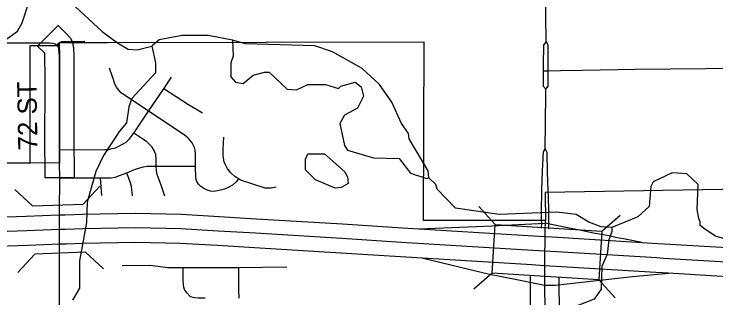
# Model space of a CAD drawing. Extents: x -1403959 to 81668, y -1400582 to 11018.
# Drawn here: x 6695.1 to 6835.6, y 8666.3 to 8723.2 of the extents above; entities that cross this region are included whole.
import ezdxf

# ---------------------------------------------------------------- set-up
doc = ezdxf.new("R2010")
doc.units = 0
for name, color, linetype in [('tdCiAirportTxt', 7, 'Continuous'), ('tdCiCityCartoShort', 7, 'Continuous'), ('tdCiCityDivCarto', 7, 'Continuous'), ('tdCiCityStreetTxt', 7, 'Continuous'), ('tdCiCoBndryTxt', 7, 'Continuous'), ('tdCiRRCL', 7, 'Continuous'), ('tdCiSectLine', 7, 'Continuous'), ('tdCiSectNmbr', 7, 'Continuous'), ('tdCiSectTwpRng', 7, 'Continuous'), ('tdCoCityStreetMajor', 7, 'Continuous'), ('tdCoDivCarto', 7, 'Continuous'), ('tdCoPriCL', 7, 'Continuous'), ('tdCoSectNmbr', 7, 'Continuous'), ('tdCoSurfBitum', 7, 'Continuous'), ('tdCoSurfEarth', 7, 'Continuous')]:
    doc.layers.add(name, color=color, linetype=linetype)

msp = doc.modelspace()

# ---------------------------------------------------------------- linework, layer by layer
at = {"layer": 'tdCiAirportTxt'}
for points in [[(6656.54, 8681.26), (6697.52, 8682.67), (6704.05, 8682.91), (6705.25, 8682.95), (6705.29, 8682.95), (6708.75, 8683.09), (6719.41, 8683.29), (6728.58, 8683.07), (6736.15, 8682.63), (6743.59, 8682.17), (6760.88, 8681.11), (6772.85, 8680.35), (6799.13, 8678.75), (6801.54, 8678.6), (6803.99, 8678.45), (6823.98, 8677.22), (6825.34, 8677.14), (6845.86, 8675.9)], [(6656.78, 8675.47), (6697.73, 8676.87), (6704.27, 8677.11), (6705.47, 8677.15), (6705.51, 8677.15), (6708.92, 8677.28), (6719.4, 8677.49), (6728.34, 8677.27), (6735.8, 8676.83), (6743.24, 8676.38), (6760.52, 8675.32), (6772.49, 8674.56), (6798.77, 8672.96), (6801.19, 8672.81), (6803.64, 8672.66), (6823.61, 8671.43), (6824.98, 8671.35), (6845.51, 8670.11)]]:
    msp.add_lwpolyline(points, dxfattribs=at)
at = {"layer": 'tdCiCityCartoShort'}
msp.add_lwpolyline([(6845.68, 8672.98), (6825.15, 8674.21), (6823.79, 8674.3), (6803.81, 8675.53), (6801.36, 8675.68), (6798.94, 8675.82), (6772.66, 8677.42), (6760.69, 8678.18), (6743.41, 8679.25), (6735.97, 8679.7), (6728.46, 8680.14), (6719.4, 8680.36), (6708.83, 8680.16), (6705.39, 8680.03), (6705.35, 8680.02), (6704.15, 8679.98), (6697.62, 8679.74), (6656.66, 8678.34)], dxfattribs=at)
at = {"layer": 'tdCiCityDivCarto'}
for points in [[(6802.08, 8686.96), (6802.07, 8687.43)], [(6802.09, 8686.82), (6802.08, 8686.96)], [(6802.09, 8686.8), (6802.09, 8686.82)], [(6802.18, 8681.15), (6802.2, 8683.46), (6802.09, 8686.8)], [(6802.17, 8680.11), (6802.18, 8681.15)]]:
    msp.add_lwpolyline(points, dxfattribs=at)
at = {"layer": 'tdCiCityStreetTxt'}
for p, q in [((6791.4, 8680.98), (6788.17, 8684.64)), ((6791.4, 8680.98), (6788.17, 8684.64)), ((6812.8, 8679.67), (6816.45, 8682.89)), ((6812.8, 8679.67), (6816.45, 8682.89)), ((6790.8, 8671.26), (6791.4, 8680.98)), ((6790.8, 8671.26), (6791.4, 8680.98)), ((6791.4, 8680.98), (6812.8, 8679.67)), ((6791.4, 8680.98), (6812.8, 8679.67)), ((6812.8, 8679.67), (6812.2, 8669.94)), ((6812.8, 8679.67), (6812.2, 8669.94)), ((6790.8, 8671.26), (6787.15, 8668.03)), ((6790.8, 8671.26), (6787.15, 8668.03)), ((6812.2, 8669.94), (6790.8, 8671.26)), ((6790.8, 8671.26), (6790.8, 8671.26)), ((6812.2, 8669.94), (6790.8, 8671.26)), ((6790.8, 8671.26), (6790.8, 8671.26)), ((6812.2, 8669.94), (6815.43, 8666.29)), ((6812.2, 8669.94), (6815.43, 8666.29))]:
    msp.add_line(p, q, dxfattribs=at)
at = {"layer": 'tdCiCoBndryTxt'}
for points in [[(6703.89, 8716.76), (6703.88, 8716.76)], [(6704.06, 8716.31), (6703.93, 8716.72), (6703.89, 8716.76)], [(6704.14, 8714.59), (6704.14, 8714.6), (6704.06, 8716.31)], [(6704.19, 8693.27), (6704.16, 8695.99), (6704.17, 8710.68), (6704.14, 8714.59)]]:
    msp.add_lwpolyline(points, dxfattribs=at)
at = {"layer": 'tdCiRRCL'}
for points in [[(6848.72, 8688.25), (6801.43, 8687.43), (6801.46, 8685.43), (6801.48, 8683.49), (6801.49, 8681.79), (6777.06, 8681.79), (6777.2, 8717.57), (6713.78, 8717.44), (6708.43, 8717.42), (6706.23, 8717.41), (6704.12, 8717.4), (6704.12, 8716.84), (6698.23, 8716.8), (6698.23, 8693.26), (6680, 8693.38)], [(6801.41, 8662.65), (6801.4, 8670.2), (6801.37, 8673.4), (6801.4, 8675.71), (6801.41, 8676.89), (6801.47, 8680.17), (6801.5, 8681.16), (6801.49, 8681.79), (6777.06, 8681.79), (6777.2, 8717.57), (6713.78, 8717.44), (6708.43, 8717.42), (6706.23, 8717.41), (6704.12, 8717.4), (6704.14, 8714.6), (6704.17, 8710.68), (6704.16, 8695.99), (6704.19, 8693.27), (6680.19, 8693.38)]]:
    msp.add_lwpolyline(points, dxfattribs=at)
at = {"layer": 'tdCiSectLine'}
msp.add_lwpolyline([(6701.31, 8690.34), (6701.29, 8693.24), (6701.26, 8695.97), (6701.26, 8695.99), (6701.26, 8695.99), (6701.27, 8710.67), (6701.24, 8714.52), (6701.2, 8715.34), (6699.78, 8716.77), (6703.88, 8720.87), (6705.94, 8718.81), (6705.98, 8718.77), (6706.11, 8718.63), (6706.23, 8718.48), (6706.34, 8718.33), (6706.44, 8718.17), (6706.53, 8718), (6706.61, 8717.83), (6706.68, 8717.65), (6706.68, 8717.64), (6706.82, 8717.23), (6706.87, 8717.06), (6706.91, 8716.88), (6706.94, 8716.69), (6706.96, 8716.5), (6706.96, 8716.44), (6707.04, 8714.73), (6707.04, 8714.62), (6707.07, 8710.7), (6707.07, 8710.68), (6707.07, 8710.68), (6707.07, 8696), (6707.09, 8693.3), (6707.12, 8690.39), (6701.31, 8690.34)], dxfattribs=at)
at = {"layer": 'tdCiSectNmbr'}
for points in [[(6801.65, 8717.7), (6801.59, 8722.88), (6801.54, 8730.02), (6801.56, 8733.6)], [(6801.65, 8717.7), (6801.1, 8716.96), (6801.06, 8712.99), (6801.03, 8711.82), (6801.03, 8708.74), (6801.58, 8708.16)], [(6801.58, 8708.16), (6802.02, 8708.74), (6802.04, 8711.83), (6802.06, 8713.75), (6802.04, 8716.93), (6801.65, 8717.69)], [(6801.65, 8717.69), (6801.65, 8717.7)], [(6801.57, 8707.6), (6801.58, 8708.16)], [(6801.43, 8696.53), (6801.5, 8701.01), (6801.57, 8707.58)], [(6801.57, 8707.58), (6801.57, 8707.6)], [(6801.42, 8696.25), (6801.04, 8695.54), (6800.82, 8691.73), (6800.68, 8687.93), (6800.68, 8687.41)], [(6801.43, 8696.24), (6801.42, 8696.25), (6801.43, 8696.53)], [(6801.71, 8695.71), (6801.43, 8696.24)], [(6801.71, 8695.71), (6801.71, 8695.71)], [(6802.07, 8687.44), (6802.05, 8687.91), (6801.89, 8691.52), (6801.84, 8695.46), (6801.71, 8695.71)], [(6704.18, 8683.41), (6704.22, 8690.39), (6704.19, 8693.27)], [(6800.68, 8687.41), (6800.69, 8686.45), (6800.66, 8684.89), (6800.66, 8683.86), (6800.67, 8681.79)], [(6802.07, 8687.43), (6802.07, 8687.44)], [(6704.46, 8620.73), (6704.46, 8632.32), (6704.47, 8640.48), (6704.51, 8642.83), (6704.52, 8653.26), (6704.22, 8657.62), (6704.18, 8663.6), (6704.19, 8664.65), (6704.18, 8676.24), (6704.2, 8680.01), (6704.18, 8683.41), (6704.18, 8683.41)], [(6800.67, 8681.79), (6800.68, 8681.34), (6800.66, 8680.24)]]:
    msp.add_lwpolyline(points, dxfattribs=at)
at = {"layer": 'tdCiSectTwpRng'}
for points in [[(6704.12, 8717.4), (6704.61, 8717.7), (6709.27, 8717.73)], [(6679.76, 8717.52), (6680.01, 8717.51), (6690.85, 8717.44), (6702.24, 8717.42), (6702.82, 8717.38), (6703.29, 8717.24), (6703.67, 8716.98)], [(6703.67, 8716.98), (6703.69, 8716.96)], [(6703.69, 8716.96), (6704.12, 8717.4)], [(6703.88, 8716.76), (6703.69, 8716.96)], [(6739.99, 8690.19), (6739.57, 8689.58), (6738.81, 8688.89), (6738.1, 8688.5), (6737.23, 8688.08), (6736.18, 8687.79), (6735.11, 8687.63), (6734.4, 8687.7), (6733.61, 8687.98), (6733.03, 8688.26), (6732.47, 8688.61), (6732.02, 8689.08), (6731.68, 8689.63), (6731.46, 8690.29), (6731.43, 8692.69), (6731.41, 8695.18), (6731.34, 8695.92), (6731.19, 8696.45), (6731.02, 8696.84), (6730.73, 8697.4), (6730.38, 8697.8), (6730.08, 8698.16), (6729.84, 8698.4), (6729.17, 8698.95), (6722, 8703.7), (6716.55, 8707.4), (6716.06, 8707.9), (6715.61, 8708.51), (6715.24, 8709.16), (6714.96, 8710.06), (6714.7, 8710.83), (6714.2, 8712.33)], [(6801.54, 8711.82), (6802.04, 8711.83), (6804.54, 8711.85), (6808.96, 8711.97), (6819.49, 8712.14), (6833.59, 8712.29), (6841.18, 8712.43), (6846.86, 8712.64), (6852.7, 8712.76)], [(6801.03, 8711.82), (6801.48, 8711.82)], [(6704.16, 8695.99), (6713.27, 8696.06), (6714.01, 8696.06), (6714.69, 8696.22), (6715.36, 8696.37), (6716.08, 8696.69), (6716.82, 8697.09), (6717.51, 8697.54), (6718.18, 8698.17), (6719.03, 8699.29), (6720.1, 8700.9), (6722, 8703.7), (6725.09, 8708.23), (6726.62, 8710.54)], [(6732.79, 8703.3), (6730.02, 8704.96), (6725.09, 8708.23)], [(6725.29, 8686.7), (6724.59, 8688.68), (6723.76, 8691.04), (6723.61, 8691.73), (6723.54, 8692.68), (6723.54, 8694.13), (6723.45, 8694.99), (6723.18, 8695.68), (6722.71, 8696.49), (6722.13, 8697.11), (6721.57, 8697.61), (6720.86, 8698.1), (6719.03, 8699.29)], [(6747.57, 8688.46), (6746.59, 8688.28), (6746.09, 8688.26), (6745.38, 8688.31), (6740.45, 8689.9), (6739.99, 8690.19), (6739.63, 8690.41), (6739.28, 8690.63), (6738.58, 8691.3), (6737.85, 8692.18), (6737.43, 8692.98), (6737.17, 8693.56), (6737.01, 8694.31), (6736.92, 8694.94), (6736.92, 8696.11), (6737.08, 8698.49)], [(6704.22, 8690.39), (6712.38, 8690.39), (6713.62, 8690.39), (6714.49, 8690.39), (6715.3, 8690.52), (6716.16, 8690.81), (6717.68, 8691.37), (6719.19, 8692), (6720.26, 8692.38), (6720.98, 8692.59), (6721.68, 8692.68), (6722.55, 8692.68), (6723.54, 8692.68), (6731.43, 8692.69)], [(6718.78, 8686.73), (6718.58, 8688.59), (6718.4, 8689.33), (6718.07, 8690.23), (6717.68, 8691.37)], [(6712.63, 8686.84), (6712.38, 8690.39)], [(6716.7, 8672.81), (6722.21, 8672.85), (6723.95, 8672.67), (6725.78, 8672.4), (6728.91, 8672.38), (6740.07, 8672.4), (6749.68, 8672.49)], [(6733.34, 8666.21), (6731.98, 8666.23), (6731.18, 8666.28), (6730.43, 8666.53), (6729.65, 8667.29), (6729.2, 8667.99), (6729, 8668.74), (6728.96, 8670.05), (6728.91, 8672.38)], [(6740.11, 8669.32), (6740.07, 8672.4)], [(6740.16, 8666.24), (6740.11, 8667.89), (6740.11, 8669.32)]]:
    msp.add_lwpolyline(points, dxfattribs=at)
at = {"layer": 'tdCoCityStreetMajor'}
msp.add_lwpolyline([(6706.69, 8717.44), (6708.39, 8717.46)], dxfattribs=at)
at = {"layer": 'tdCoDivCarto'}
for points in [[(6798.46, 8670.79), (6798.47, 8662.71), (6798.29, 8657.09), (6798.23, 8642.32), (6798.25, 8614.6), (6798.54, 8603.08), (6798.45, 8589.41), (6797.96, 8577.77), (6797.92, 8572.93), (6797.52, 8548.32), (6797.6, 8524.16), (6797.72, 8518.4)], [(6808.38, 8527.11), (6808.02, 8527.11), (6803.34, 8527.12), (6803.32, 8548.23), (6803.72, 8572.87), (6803.76, 8577.58), (6804.25, 8589.25), (6804.35, 8603.14), (6804.05, 8614.71), (6804.03, 8642.25), (6804.09, 8656.93), (6804.28, 8662.6), (6804.27, 8670.43)]]:
    msp.add_lwpolyline(points, dxfattribs=at)
at = {"layer": 'tdCoPriCL'}
for points in [[(6776.27, 8680.14), (6790.79, 8680.72), (6801.46, 8681.28)], [(6808.29, 8679.86), (6804.26, 8680.7), (6801.46, 8681.28)], [(6811.14, 8679.29), (6808.29, 8679.86)], [(6814.28, 8678.74), (6811.14, 8679.29)], [(6817.11, 8678.11), (6815.83, 8678.3), (6814.28, 8678.74)], [(6820.82, 8677.41), (6817.11, 8678.11)], [(6776.73, 8674.31), (6790.29, 8671.08)], [(6801.37, 8668.82), (6803.45, 8668.86), (6818.96, 8670.61), (6826.19, 8671.27)], [(6790.29, 8671.08), (6794.42, 8670.23)], [(6794.42, 8670.23), (6801.37, 8668.82)]]:
    msp.add_lwpolyline(points, dxfattribs=at)
at = {"layer": 'tdCoSurfBitum'}
for points in [[(6693.16, 8717.91), (6695.76, 8719.74), (6696.68, 8721.41), (6698.06, 8725.53)], [(6706.46, 8725.51), (6712.71, 8719.7), (6715.76, 8717.4), (6717.9, 8716.18), (6719.73, 8716.02), (6722.63, 8716.77), (6723.39, 8713.41), (6723.39, 8711.43), (6718.64, 8706.25), (6718.03, 8704.57), (6717.56, 8701.37), (6716.18, 8699.69), (6712.97, 8694.81), (6711.43, 8691.61), (6709.74, 8685.51), (6709.58, 8681.38), (6708.19, 8673.75), (6708.18, 8668.26), (6706.8, 8665.82)], [(6738.82, 8717.96), (6733.94, 8718.89), (6728.75, 8718.9), (6724.16, 8717.99), (6722.63, 8716.77)], [(6814.8, 8680.38), (6812.66, 8680.54), (6810.22, 8681.46), (6807.63, 8683), (6803.81, 8683.46), (6792.2, 8683.03), (6783.5, 8684.27), (6779.84, 8688.1), (6779.54, 8689.01), (6778.17, 8690.39), (6778.02, 8691.76), (6774.21, 8698.19), (6774.06, 8699.25), (6772.69, 8701.24), (6770.71, 8705.52), (6768.28, 8709.04), (6764.77, 8712.25), (6758.82, 8715.63), (6755.31, 8716.85), (6741.42, 8717.19), (6738.82, 8717.96), (6738.97, 8714.75), (6738.51, 8713.38), (6738.5, 8710.63), (6739.42, 8709.56), (6740.94, 8709.25), (6742.93, 8710.93), (6745.22, 8711.53), (6746.14, 8711.53), (6749.8, 8708.16), (6751.63, 8708.01), (6753.92, 8709.07), (6757.44, 8709.06), (6760.03, 8708.29), (6760.49, 8708.75), (6763.39, 8709.51), (6764.61, 8708.59), (6765.07, 8706.76), (6763.84, 8704.32), (6761.24, 8702.95), (6760.32, 8701.27), (6761.23, 8696.84), (6761.84, 8695.92), (6767.03, 8694.38), (6772.22, 8694.22), (6774.5, 8691.31), (6777.71, 8690.24), (6778.17, 8690.39)], [(6759.38, 8688.29), (6755.41, 8689.98), (6753.43, 8691.97), (6753.43, 8694.11), (6753.89, 8695.18), (6757.25, 8695.17), (6761.22, 8691.65), (6761.83, 8690.58), (6761.98, 8689.2), (6760.6, 8688.45), (6759.38, 8688.29)], [(6837.55, 8678.04), (6835.56, 8678.66), (6833.43, 8680.04), (6832.51, 8680.8), (6832.51, 8681.57), (6832.21, 8682.18), (6831.91, 8684.01), (6832.07, 8689.05), (6829.79, 8691.19), (6826.88, 8691.35), (6823.06, 8689.53), (6822.6, 8688.61), (6822.29, 8684.64), (6819.99, 8682.51), (6814.8, 8680.38), (6814.8, 8679.62), (6814.18, 8677.94), (6813.87, 8675.04), (6812.8, 8672.6), (6812.63, 8668.02), (6811.26, 8666.04), (6806.67, 8664.22), (6806.21, 8663.15)]]:
    msp.add_lwpolyline(points, dxfattribs=at)
at = {"layer": 'tdCoSurfEarth'}
for p, q in [((6708.94, 8685.1), (6712.25, 8688.68)), ((6698.77, 8684.72), (6695.2, 8688.03)), ((6698.77, 8684.72), (6708.94, 8685.1)), ((6699.21, 8675.05), (6695.83, 8671.4)), ((6709.39, 8675.44), (6699.21, 8675.05)), ((6709.39, 8675.44), (6712.97, 8672.13))]:
    msp.add_line(p, q, dxfattribs=at)

# ---------------------------------------------------------------- texts
at = {"layer": 'tdCoSectNmbr'}
msp.add_text('72 ST', height=3.869, rotation=91, dxfattribs=at).set_placement((6699.78, 8695.9))

doc.saveas('drawing.dxf')
